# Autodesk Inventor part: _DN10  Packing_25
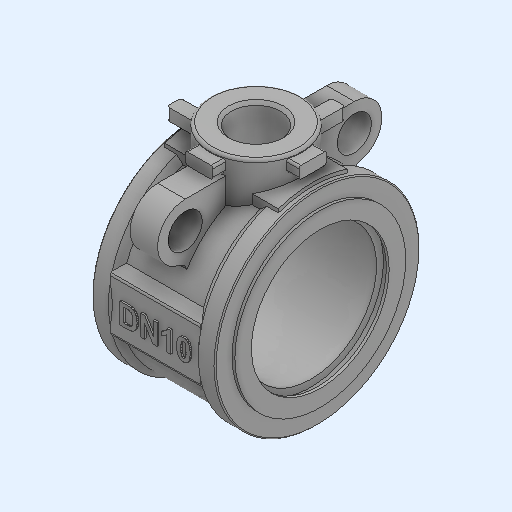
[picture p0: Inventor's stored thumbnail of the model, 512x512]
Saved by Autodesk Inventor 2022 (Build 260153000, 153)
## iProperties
Created: 2021-12
Part Number: _DN10  Packing_25
Material: Generico
Document SubType Name: Modeling
Designer: admin
Density: 1 g/cm^3
Appearance: Default
Author: admin
Revision Number: NONE
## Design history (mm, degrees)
feature "_DN10  Packing"
node "Solido1"
